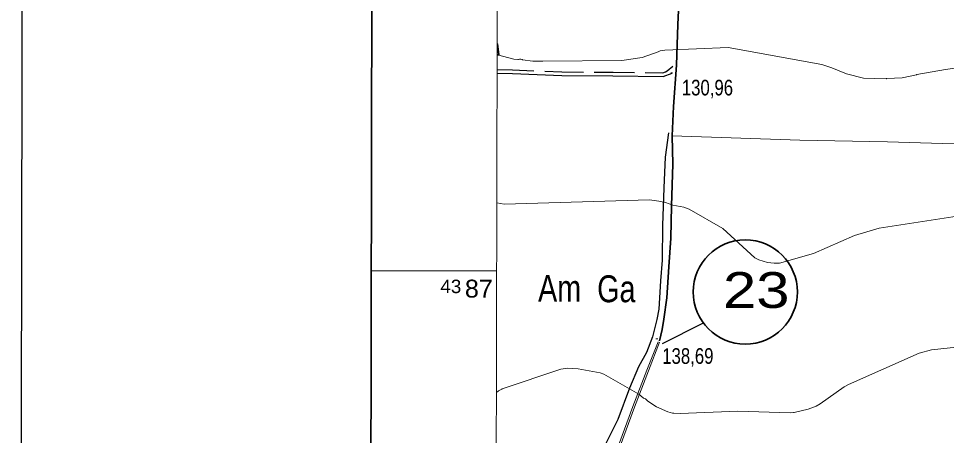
# Model space of a CAD drawing. Extents: x 483840 to 488445, y 4386047 to 4389027.
# Drawn here: x 483840 to 484358, y 4386908 to 4387141 of the extents above; entities that cross this region are included whole.
import ezdxf
from ezdxf.enums import TextEntityAlignment as Align

# ---------------------------------------------------------------- set-up
doc = ezdxf.new("R2010")
doc.units = 0
doc.header["$LTSCALE"] = 4
for name, pattern in [('DOTTED', [1.5, 0.3, -1.2]), ('LONG_DASHED', [7.5, 6, -1.5]), ('MEDIUM_DASHED', [4.5, 3, -1.5])]:
    doc.linetypes.add(name, pattern=pattern)
for name, color, linetype, lineweight in [('1', 7, 'Continuous', 13), ('13', 7, 'Continuous', 25), ('2', 7, 'DOTTED', 13), ('25', 7, 'LONG_DASHED', 25), ('38', 7, 'Continuous', 25), ('47', 7, 'Continuous', 35), ('51', 7, 'Continuous', 13), ('6', 7, 'Continuous', 35), ('7', 7, 'Continuous', 13), ('9', 7, 'Continuous', 13)]:
    doc.layers.add(name, color=color, linetype=linetype, lineweight=lineweight)
doc.layers.add('31', color=7, linetype='Continuous')

msp = doc.modelspace()

# ---------------------------------------------------------------- linework, layer by layer
at = {"layer": '1'}
msp.add_line((484106.69, 4387000), (484036.56, 4387000), dxfattribs=at)
at = {"layer": '1', "lineweight": 25}
msp.add_lwpolyline([(483845.33, 4389027.42), (488445.32, 4389018.55), (488439.58, 4386047.03), (483839.59, 4386055.9), (483845.33, 4389027.2)], dxfattribs=at)
at = {"layer": '1', "lineweight": 35}
msp.add_lwpolyline([(484040.1, 4388831.88), (487756.5, 4388824.71), (487751.76, 4386369.72), (484035.36, 4386376.89)], close=True, dxfattribs=at)
at = {"layer": '1'}
msp.add_lwpolyline([(484110.5, 4388760.3), (487685.8, 4388753.5), (487681.9, 4386441.2), (484105.5, 4386448.1)], close=True, dxfattribs=at)
at = {"layer": '25'}
msp.add_lwpolyline([(484202.64, 4387077.08), (484200.68, 4387063.34), (484200, 4387046.26), (484199.25, 4387025.29), (484199.04, 4387005.97), (484198.07, 4386994.39), (484197.21, 4386978.48), (484196.03, 4386972.72), (484193.75, 4386963.07), (484190.26, 4386954.32), (484185.8, 4386946.36), (484180.87, 4386934.45), (484174.32, 4386916.91), (484166.1, 4386900.52), (484160.04, 4386887.99), (484158.86, 4386886.19), (484132.58, 4386887.55), (484114.07, 4386888.28)], dxfattribs=at)
at = {"layer": '38', "linetype": 'MEDIUM_DASHED'}
msp.add_lwpolyline([(484106.94, 4387112.39), (484115.47, 4387112.21), (484143.09, 4387111.01), (484171.62, 4387110.84), (484199.35, 4387110.5), (484200.89, 4387111.09), (484201.83, 4387111.58), (484205, 4387114.2)], dxfattribs=at)
at = {"layer": '38'}
msp.add_lwpolyline([(484106.93, 4387110.37), (484115.41, 4387110.2), (484143.04, 4387109), (484171.6, 4387108.83), (484199.71, 4387108.48), (484204.71, 4387110.39)], dxfattribs=at)
at = {"layer": '38', "lineweight": 13}
for points in [[(484196.79, 4386960.29), (484190.43, 4386944.41), (484182.7, 4386924.24), (484174.6, 4386902.33), (484170.89, 4386890.12), (484171.58, 4386884.27), (484172.2, 4386882.87), (484174.15, 4386880.59), (484177.01, 4386879.27), (484191.82, 4386875.34), (484200.09, 4386873.57), (484206.39, 4386872.96), (484217.81, 4386873.23), (484228.87, 4386872.07), (484234.61, 4386869.83), (484244.23, 4386865.96), (484250.27, 4386862.07), (484254.4, 4386854.83)], [(484197.55, 4386960.14), (484191.38, 4386944.05), (484183.65, 4386923.88), (484175.56, 4386902.01), (484171.92, 4386890.03), (484172.57, 4386884.54), (484173.07, 4386883.42), (484174.78, 4386881.42), (484177.36, 4386880.23), (484192.06, 4386876.33), (484200.25, 4386874.58), (484206.43, 4386873.98), (484217.85, 4386874.25), (484229.11, 4386873.07), (484234.98, 4386870.77), (484244.7, 4386866.87), (484251, 4386862.81), (484255.48, 4386854.78)]]:
    msp.add_lwpolyline(points, dxfattribs=at)
at = {"layer": '47'}
msp.add_lwpolyline([(484106.95, 4387120.53), (484107.85, 4387120.56), (484107.17, 4387126.69), (484106.97, 4387126.68)], dxfattribs=at)
at = {"layer": '51'}
msp.add_lwpolyline([(484204.57, 4387075.31), (484276.04, 4387072.84), (484324.95, 4387072.01), (484355.69, 4387070.99), (484402.04, 4387069.68), (484441.54, 4387069.09), (484498.66, 4387067.93)], dxfattribs=at)
at = {"layer": '6', "lineweight": 25}
msp.add_line((484199.3, 4386959.43), (484221.83, 4386970.68), dxfattribs=at)
at = {"layer": '6'}
msp.add_lwpolyline([(484212.82, 4387295.28), (484212.47, 4387278.4), (484211.44, 4387240.58), (484210.65, 4387220.54), (484209.3, 4387209.89), (484208.08, 4387198.84), (484207.98, 4387189.84), (484208.12, 4387179.31), (484208.42, 4387167.67), (484208.7, 4387158.03), (484208.44, 4387149.25), (484207.87, 4387137.58), (484207.04, 4387114.72), (484205.45, 4387091.7), (484204.57, 4387075.39), (484204.95, 4387059.47), (484204.36, 4387036.27), (484203.86, 4387018.17), (484202.77, 4387002.21), (484201.65, 4386984.79), (484200.05, 4386972.86), (484199.05, 4386967.22), (484197.58, 4386960.92), (484197.54, 4386960.81)], dxfattribs=at)
msp.add_circle((484245.51, 4386988.12), 29.1, dxfattribs=at)
at = {"layer": '7'}
for p, q in [((484203.91, 4387110.6), (484204.91, 4387110.6)), ((484195.61, 4386962.03), (484196.61, 4386962.03))]:
    msp.add_line(p, q, dxfattribs=at)
at = {"layer": '9'}
for points in [[(484364.03, 4387113.27), (484357.35, 4387112.39), (484341.34, 4387109.63), (484341.11, 4387109.48), (484333.04, 4387107.8), (484324.56, 4387107.26), (484324.38, 4387107.3), (484324.33, 4387107.3), (484324.29, 4387107.3), (484324.13, 4387107.25), (484311.5, 4387107.46), (484302.04, 4387109.89), (484293.86, 4387113.25), (484288.24, 4387115.25), (484235.9, 4387124.71), (484200.58, 4387123.2), (484197.92, 4387122.72), (484197.13, 4387122.46), (484196.88, 4387122.33), (484187.94, 4387119.06), (484176.49, 4387117.33), (484132.45, 4387117.02), (484127.09, 4387117.04), (484127.07, 4387117.04), (484126.75, 4387117.05), (484121.11, 4387117.82), (484120.86, 4387117.92), (484120.76, 4387117.95), (484120.11, 4387118.06), (484119.36, 4387118.11), (484118.77, 4387118.01), (484118.45, 4387118), (484116.17, 4387118.18), (484107.1, 4387120.53)], [(484106.78, 4387037.89), (484110.87, 4387037.26), (484192.04, 4387039.54), (484197.26, 4387038.93), (484200.88, 4387038.02), (484205.1, 4387036.55), (484211.09, 4387035.48), (484214.07, 4387034.34), (484232.94, 4387023.58), (484250.9, 4387007.22), (484253.02, 4387006.13), (484257.9, 4387004.59), (484261.57, 4387004.15), (484264.64, 4387004.26), (484283.68, 4387009.71), (484306.54, 4387019.64), (484320.26, 4387023.68), (484373.58, 4387032.02)], [(484106.55, 4386932.06), (484107.64, 4386932.85), (484109.53, 4386933.9), (484109.73, 4386933.98), (484142.46, 4386945.04), (484146.18, 4386945.51), (484152.13, 4386945.28), (484164.52, 4386942.92), (484166.55, 4386942.22), (484186, 4386930.98), (484188.37, 4386929.04), (484188.7, 4386928.85), (484189.39, 4386928.59), (484189.76, 4386928.4), (484189.97, 4386928.23), (484191.01, 4386927.06), (484195.94, 4386923.94), (484202.25, 4386921.16), (484204.77, 4386920.47), (484205.52, 4386920.36), (484209.07, 4386920.3), (484241.4, 4386921.63), (484270.5, 4386920.7), (484272.51, 4386920.86), (484272.76, 4386920.86), (484280.55, 4386922.62), (484285.08, 4386924.41), (484287.24, 4386925.59), (484300.73, 4386935.2), (484303.05, 4386936.5), (484342.68, 4386953.89), (484349.49, 4386955.74), (484427.81, 4386964.27)]]:
    msp.add_lwpolyline(points, dxfattribs=at)

# ---------------------------------------------------------------- texts
at = {"layer": '13', "width": 1.25}
msp.add_text('23', height=20, dxfattribs=at).set_placement((484251.61, 4386979.22), align=Align.CENTER)
at = {"layer": '2', "width": 1.05}
for s, height, p in [('43', 7.5, (484086.89, 4386987.5)), ('87', 10, (484104.49, 4386985))]:
    msp.add_text(s, height=height, dxfattribs=at).set_placement(p, align=Align.RIGHT)
at = {"layer": '31', "width": 0.8}
for s, p in [('Am', (484141.79, 4386982.68)), ('Ga', (484173.47, 4386982.41))]:
    msp.add_text(s, height=15, dxfattribs=at).set_placement(p, align=Align.CENTER)
at = {"layer": '7', "width": 0.8}
for s, p in [('130,96', (484210.04, 4387097.89)), ('138,69', (484199.1, 4386947.99))]:
    msp.add_text(s, height=8.75, dxfattribs=at).set_placement(p)

doc.saveas('drawing.dxf')
